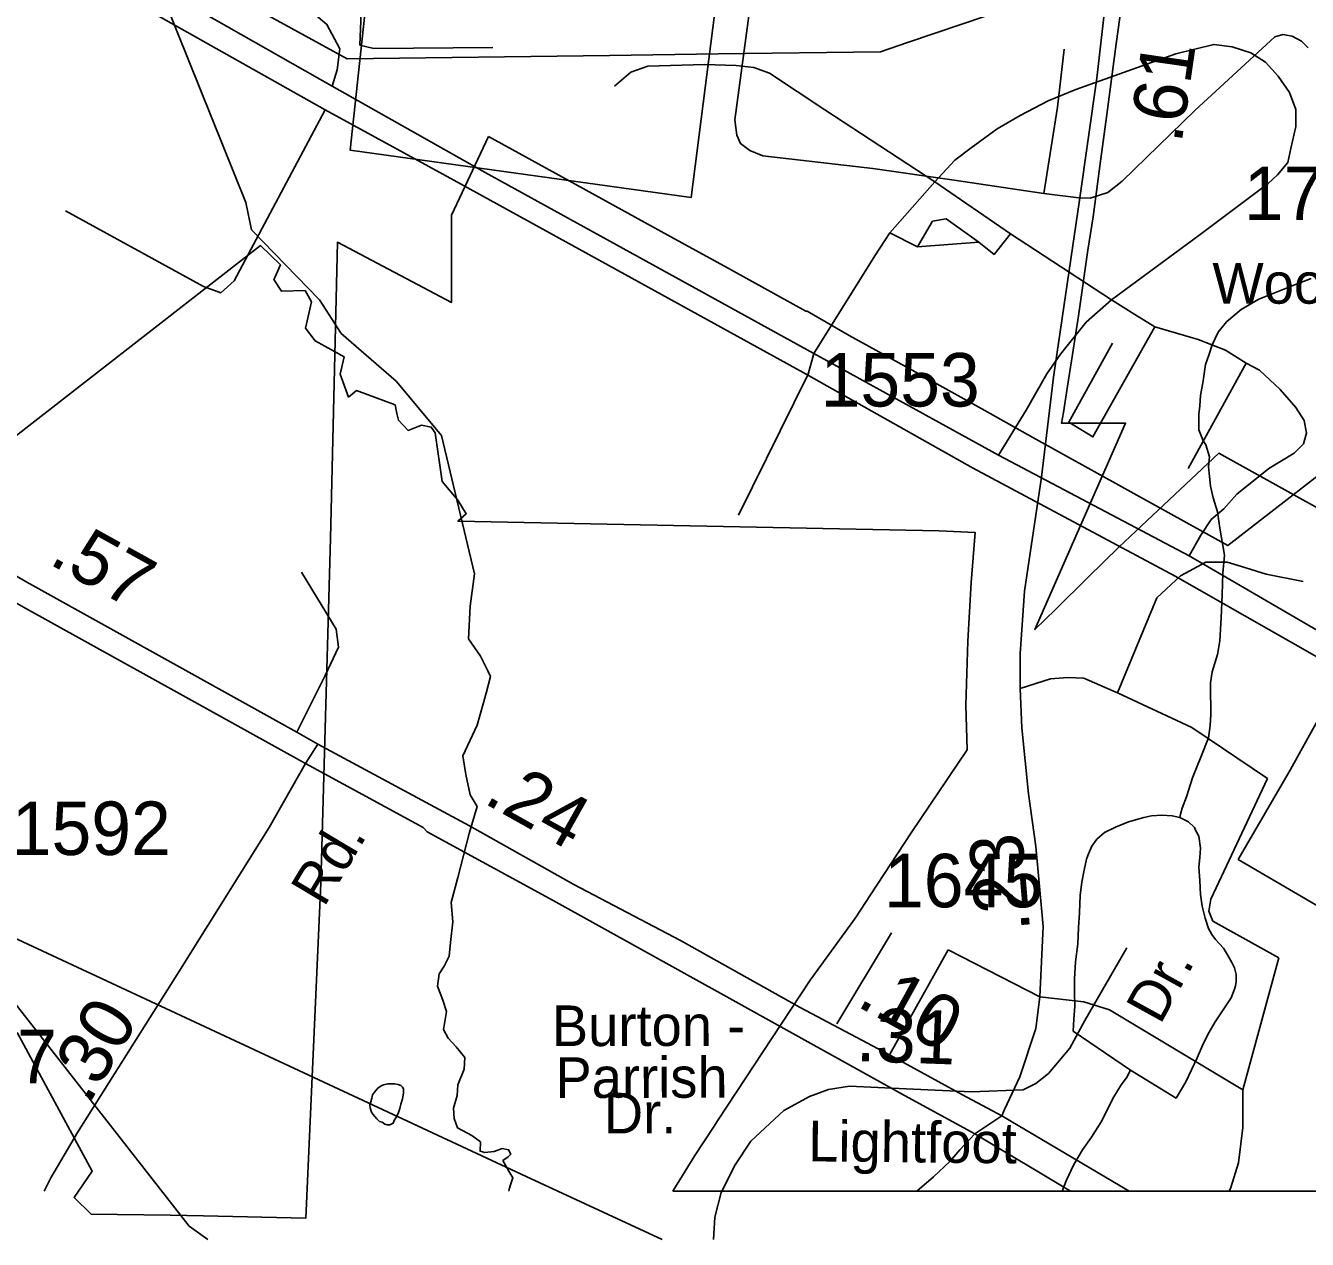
# Model space of a CAD drawing. Extents: x 2169602 to 2449496, y 721995 to 810662.
# Drawn here: x 2392905 to 2395899, y 758895 to 761731 of the extents above; entities that cross this region are included whole.
import ezdxf

# ---------------------------------------------------------------- set-up
doc = ezdxf.new("R2010")
doc.units = 0
doc.layers.add('Default', color=7, linetype='Continuous')

msp = doc.modelspace()

# ---------------------------------------------------------------- linework, layer by layer
at = {"layer": 'Default'}
for p, q in [((2393694.4, 761900.1), (2393685.4, 761684.9)), ((2394923.5, 761246.5), (2395028.4, 761365.8)), ((2395205.6, 761244.7), (2395028.4, 761365.8)), ((2394988.6, 761213.9), (2395022.9, 761273.6)), ((2395022.9, 761273.6), (2395055.5, 761279)), ((2395055.5, 761279), (2395131.5, 761224.8)), ((2394923.5, 761246.5), (2394988.6, 761213.9)), ((2395167.6, 761195.9), (2395205.6, 761244.7)), ((2395205.6, 761244.7), (2395441.6, 761090.1)), ((2394988.6, 761213.9), (2395131.5, 761224.8)), ((2395131.5, 761224.8), (2395167.6, 761195.9)), ((2395756.3, 760941.8), (2395620.6, 760695.8)), ((2394799.7, 759398.8), (2394927.2, 759611.2)), ((2395060.1, 759571.5), (2394923.1, 759326.2)), ((2395274.4, 759461.5), (2395060.1, 759571.5)), ((2395748.1, 759244.5), (2395832.6, 759552.6)), ((2394416.8, 759007.9), (2405610.9, 759007.9)), ((2394416.8, 759007.9), (2405610.9, 759007.9))]:
    msp.add_line(p, q, dxfattribs=at)
for points in [[(2393587.2, 760051.8), (2393538.6, 760080.4), (2392907.2, 760430.4), (2392607.1, 760604.7), (2392161.9, 760840.1), (2391730.4, 761078), (2390962.6, 761500.1), (2390605.2, 761701.9), (2389990.5, 762051.8), (2389856.7, 762127.7), (2389737.8, 762198.8), (2389440.2, 762351.9), (2389076.5, 762551.2), (2388547.4, 762852.9), (2388224.1, 763014.5), (2387185.5, 763596), (2386852.4, 763781.6), (2386637.1, 763912.4), (2386426.2, 764027.4), (2386153.7, 764163.9)], [(2386150.4, 764102.4), (2386756.5, 763764.2), (2388207.3, 762942.2), (2388747.6, 762648.7), (2389706.7, 762136.5), (2390036.6, 761958.6), (2390589, 761647.1), (2390889.1, 761482.7), (2391705.4, 761033.1), (2392100.8, 760810.2), (2392574.7, 760557.4), (2392899.7, 760371.9), (2393558.4, 760007.1)], [(2396603, 759939), (2396554.4, 759967.6), (2395923, 760317.6), (2395622.9, 760491.9), (2395177.7, 760727.3), (2394746.2, 760965.1), (2393978.4, 761387.3), (2393621, 761589.1), (2393006.3, 761938.9), (2392872.5, 762014.9), (2392753.6, 762085.9), (2392456, 762239.1), (2392092.4, 762438.4), (2391563.2, 762740), (2391239.9, 762901.6), (2390201.3, 763483.2), (2389868.2, 763668.8), (2389653, 763799.6), (2389442, 763914.6), (2389169.5, 764051.1)], [(2389166.2, 763989.6), (2389772.3, 763651.3), (2391223.1, 762829.4), (2391763.5, 762535.9), (2392722.5, 762023.7), (2393052.4, 761845.8), (2393604.8, 761534.3), (2393905, 761369.9), (2394721.3, 760920.3), (2395116.7, 760697.4), (2395590.5, 760444.6), (2395915.6, 760259), (2396574.3, 759894.3)], [(2395185.2, 759183.4), (2395191.7, 759198.2), (2395227.3, 759274.7), (2395264.6, 759388), (2395274.4, 759461.5), (2395282.1, 759625.9), (2395264.6, 759812.7), (2395247.5, 759935.8), (2395231.7, 760090.3), (2395228, 760182.1), (2395228, 760263.3), (2395237.9, 760409.1), (2395277.7, 760675.8), (2395305.8, 760909.3), (2395366.7, 761322.6), (2395407, 761608.2), (2395431.6, 761819.5), (2395459.4, 762022.6), (2395487.1, 762218), (2395516.8, 762436.2), (2395579.2, 762896), (2395622.1, 763235.2), (2395654.9, 763535.4)], [(2395928.5, 762403.9), (2395891.5, 762227.2), (2395845.2, 762019.2), (2395840.7, 761986.6), (2395737, 761951.6), (2395433.7, 761849.2), (2395211.5, 761774.3), (2394965.2, 761691.2), (2394902, 761669.9), (2394522.2, 761664.7), (2394268.7, 761661.2), (2393656, 761652.8), (2393320.5, 761837.6), (2393242.7, 761881.4), (2393240.7, 761882.4), (2393165.7, 761922.9), (2392899.5, 762066.6)], [(2395928.5, 762403.9), (2395891.5, 762227.2), (2395845.2, 762019.2), (2395840.7, 761986.6), (2395737, 761951.6), (2395433.7, 761849.2), (2395211.5, 761774.3), (2394965.2, 761691.2), (2394902, 761669.9), (2394522.2, 761664.7), (2394268.7, 761661.2), (2393656, 761652.8), (2393320.5, 761837.6), (2393242.7, 761881.4), (2393240.7, 761882.4), (2393165.7, 761922.9), (2392899.5, 762066.6)], [(2393424.1, 761949.8), (2393444.9, 761900.1), (2393470.2, 761858.5), (2393506.4, 761820.5), (2393608.6, 761733.5), (2393626, 761699.9), (2393638.4, 761676.2), (2393632.2, 761627.7), (2393621, 761589.1)], [(2395283.6, 761338.5), (2395073.9, 761369.6), (2394883.9, 761396.9), (2394627.3, 761426.9), (2394596.7, 761438.9), (2394574.9, 761455.3), (2394566.1, 761475), (2394561.8, 761511), (2394608.7, 761864.3)], [(2396107.2, 760501.1), (2395692.4, 760731.8), (2395511.4, 760562.1), (2395458.4, 760512.6), (2395387.2, 760442.5), (2395310.4, 760366.8), (2395262.7, 760319.8), (2395474.2, 760801.9), (2395324.9, 760801.9), (2395329.2, 760827.1), (2395338.4, 760888.4), (2395350.2, 760962.5), (2395364.7, 761053.1), (2395386.4, 761206.4), (2395398.4, 761283.7), (2395408.7, 761361.5), (2395413.9, 761402.2), (2395430.2, 761523.5), (2395452.4, 761688.3), (2395472.7, 761834.5)], [(2396107.2, 760501.1), (2395692.4, 760731.8), (2395511.4, 760562.1), (2395458.4, 760512.6), (2395387.2, 760442.5), (2395310.4, 760366.8), (2395262.7, 760319.8), (2395474.2, 760801.9), (2395324.9, 760801.9), (2395329.2, 760827.1), (2395338.4, 760888.4), (2395350.2, 760962.5), (2395364.7, 761053.1), (2395386.4, 761206.4), (2395398.4, 761283.7), (2395408.7, 761361.5), (2395413.9, 761402.2), (2395430.2, 761523.5), (2395452.4, 761688.3), (2395472.7, 761834.5)], [(2394034.4, 759007.9), (2394033.7, 759009), (2394036.8, 759020), (2394042.9, 759038.8), (2394033.7, 759054), (2394019.7, 759079), (2394031.9, 759087.5), (2394038.6, 759094.2), (2394033.1, 759104.6), (2394017.9, 759107), (2393999.1, 759100.3), (2393977.1, 759097.9), (2393966.2, 759100.9), (2393967.4, 759122.8), (2393947.3, 759137.4), (2393913.8, 759155.7), (2393905.9, 759177.6), (2393904.1, 759201.9), (2393912.6, 759231.1), (2393914.5, 759256.1), (2393929.1, 759292.6), (2393930.9, 759320), (2393910.2, 759344.9), (2393891.9, 759365), (2393881, 759385.1), (2393887.7, 759427.1), (2393879.2, 759453.9), (2393867, 759486.8), (2393870.6, 759515.4), (2393882.8, 759533.6), (2393894.4, 759556.7), (2393897.4, 759589), (2393902.9, 759637.1), (2393899.2, 759682.1), (2393914.7, 759740.5), (2393940.5, 759843.5), (2393959.5, 759906.1), (2393943.3, 759933.5), (2393933.4, 759980.8), (2393925.9, 760024.4), (2393959.5, 760096.6), (2393980.7, 760171.4), (2393990.6, 760210), (2393984.4, 760223.7), (2393967, 760257.3), (2393939.6, 760298.4), (2393943.3, 760374.3), (2393953.5, 760449.9), (2393876.6, 760772.8), (2393770.6, 760900.1), (2393642.2, 761011.5), (2393591.6, 761090.3), (2393432.4, 761253.3), (2393419.5, 761317.5), (2393231.2, 761784.2)], [(2393685.4, 761684.9), (2393717.9, 761677.6), (2393996.4, 761679.4)], [(2395441.6, 761090.1), (2395648.7, 761242.9), (2395807.8, 761362.2), (2395829.5, 761382.1), (2395853, 761411.1), (2395860.2, 761443.6), (2395872, 761495.1), (2395872, 761534.9), (2395857.5, 761574.7), (2395830.4, 761612.7), (2395801.5, 761645.2), (2395767.1, 761666.9), (2395723.7, 761681.4), (2395680.3, 761686.8), (2395591.7, 761665.1), (2395358.4, 761581.9), (2395293.3, 761554.8), (2395228.2, 761520.5), (2395174, 761489.7), (2395113.4, 761445.4), (2395075.4, 761416.5), (2395028.4, 761365.8)], [(2395391.7, 761327.5), (2395433.2, 761341.2), (2395466, 761367.4), (2395636.3, 761532.3), (2395823.1, 761704.3), (2395841.6, 761709.8), (2395863.5, 761706.5), (2395885.3, 761694.5), (2395900.6, 761679.2)], [(2395283.6, 761338.5), (2395315.3, 761540.5), (2395330.6, 761675.4)], [(2395028.4, 761365.8), (2394771.6, 761534), (2394642.3, 761619.9), (2394606.1, 761632.6), (2394564.5, 761638), (2394490.4, 761639.8), (2394358.4, 761636.2), (2394318.6, 761621.7), (2394280.6, 761589.2)], [(2393604.8, 761534.3), (2393391.9, 761134.5), (2393360.4, 761106.3), (2393320.6, 761121.2), (2392997.6, 761298.4)], [(2392884.7, 759378.6), (2393060.5, 759054.6), (2393018, 758993.1), (2393058, 758954.1), (2393242.7, 758951.2), (2393320.5, 758950), (2393559.2, 758944.4), (2393594, 759727.2), (2393616.7, 760532.9), (2393633, 761224.7), (2393899.7, 761084.1), (2393899.5, 761288.2), (2393985.7, 761471.5)], [(2392884.7, 759378.6), (2393060.5, 759054.6), (2393018, 758993.1), (2393058, 758954.1), (2393242.7, 758951.2), (2393320.5, 758950), (2393559.2, 758944.4), (2393594, 759727.2), (2393616.7, 760532.9), (2393633, 761224.7), (2393899.7, 761084.1), (2393899.5, 761288.2), (2393985.7, 761471.5)], [(2393985.7, 761471.5), (2394174.2, 761368.2), (2394366.7, 761262.6), (2394405.2, 761241.4), (2394544.7, 761164.9)], [(2393985.7, 761471.5), (2394174.2, 761368.2), (2394366.7, 761262.6), (2394405.2, 761241.4), (2394544.7, 761164.9)], [(2395391.7, 761327.5), (2395365.5, 761328.6), (2395283.6, 761338.5)], [(2394746.2, 760965.1), (2394888.2, 761193.1), (2394923.5, 761246.5)], [(2392697.2, 760628.6), (2392912.2, 760795.9), (2393453.4, 761217), (2393500.2, 761171.6), (2393487.9, 761144.1), (2393484.9, 761137.3), (2393502.4, 761110.6), (2393557.4, 761111.9), (2393572.9, 761085.7), (2393558.2, 761024.1), (2393580.9, 760994.2), (2393648.9, 760956.9), (2393639.2, 760916.5), (2393659.2, 760862.9), (2393677.9, 760878.1), (2393767.7, 760844.5), (2393772.2, 760824.3), (2393775.4, 760808.8), (2393798.7, 760785), (2393829.7, 760797.3), (2393852.4, 760792.9), (2393861.7, 760779.6), (2393877.9, 760666), (2393914.4, 760621.9), (2393934.2, 760590.4), (2393914.4, 760572.8), (2395038.7, 760550.1), (2395123.2, 760546.5), (2395113.4, 760429.4), (2395105.9, 760292.8), (2395101.2, 760142.8), (2395103.9, 760038.8), (2394973.7, 759845), (2394878.7, 759699.7), (2394843.4, 759646), (2394737.2, 759500.7), (2394627.7, 759334), (2394522.4, 759174.1), (2394511.4, 759157.3), (2394467.7, 759090.9), (2394416.8, 759007.9)], [(2392697.2, 760628.6), (2392912.2, 760795.9), (2393453.4, 761217), (2393500.2, 761171.6), (2393487.9, 761144.1), (2393484.9, 761137.3), (2393502.4, 761110.6), (2393557.4, 761111.9), (2393572.9, 761085.7), (2393558.2, 761024.1), (2393580.9, 760994.2), (2393648.9, 760956.9), (2393639.2, 760916.5), (2393659.2, 760862.9), (2393677.9, 760878.1), (2393767.7, 760844.5), (2393772.2, 760824.3), (2393775.4, 760808.8), (2393798.7, 760785), (2393829.7, 760797.3), (2393852.4, 760792.9), (2393861.7, 760779.6), (2393877.9, 760666), (2393914.4, 760621.9), (2393934.2, 760590.4), (2393914.4, 760572.8), (2395038.7, 760550.1), (2395123.2, 760546.5), (2395113.4, 760429.4), (2395105.9, 760292.8), (2395101.2, 760142.8), (2395103.9, 760038.8), (2394973.7, 759845), (2394878.7, 759699.7), (2394843.4, 759646), (2394737.2, 759500.7), (2394627.7, 759334), (2394522.4, 759174.1), (2394511.4, 759157.3), (2394467.7, 759090.9), (2394416.8, 759007.9)], [(2394544.7, 761164.9), (2394558.7, 761157.1), (2394727, 761063.7), (2394730.5, 761063.4), (2394828.7, 761007.1), (2394991, 760916.9), (2395145.5, 760831.2), (2395257.7, 760768.7), (2395544.5, 760609.4), (2395713, 760515.8), (2395928, 760683.1)], [(2394544.7, 761164.9), (2394558.7, 761157.1), (2394727, 761063.7), (2394730.5, 761063.4), (2394828.7, 761007.1), (2394991, 760916.9), (2395145.5, 760831.2), (2395257.7, 760768.7), (2395544.5, 760609.4), (2395713, 760515.8), (2395928, 760683.1)], [(2395907.7, 761140.1), (2395871.4, 761126.2), (2395835.9, 761111.7), (2395785.7, 761091.7), (2395744.3, 761067.5), (2395710.2, 761039), (2395690.5, 761014.8), (2395676.6, 760984.8), (2395668.8, 760960.9), (2395660.8, 760939), (2395655.5, 760900.9), (2395649.3, 760866.9), (2395647.5, 760842.8), (2395645.4, 760822.9), (2395645.6, 760808.6), (2395645.8, 760786.7), (2395652, 760770.8), (2395655.9, 760760.9), (2395661.8, 760751), (2395670.4, 760723), (2395668, 760701), (2395670.4, 760677.2), (2395672.7, 760654.9), (2395678.6, 760627.2), (2395689.1, 760595.2), (2395694.6, 760557), (2395705.7, 760493.3), (2395701.6, 760451.3), (2395700.2, 760401.3), (2395697.9, 760347.3), (2395694.4, 760293.4), (2395688.7, 760261.5), (2395676.8, 760221.1), (2395673.1, 760195.3), (2395673.1, 760167.3), (2395673.3, 760141.3), (2395673.5, 760121.4), (2395671.7, 760095.3), (2395667.8, 760067.1), (2395652, 760025.3), (2395640.1, 759997), (2395630.5, 759973), (2395616.7, 759928.8), (2395606.5, 759902.8), (2395602.8, 759888.7), (2395601.1, 759880.8)], [(2395441.6, 761090.1), (2395381.9, 761037.6), (2395322.2, 760963.5), (2395290.6, 760917.4), (2395241.8, 760832.4), (2395177.7, 760727.3)], [(2395441.6, 761090.1), (2395495.8, 761055.7), (2395542.9, 761026.8)], [(2395542.9, 761026.8), (2395398.2, 760770), (2395342.1, 760804.3), (2395443.4, 760988.8)], [(2395542.9, 761026.8), (2395644.1, 760997.8), (2395707.4, 760972.5), (2395756.3, 760941.8)], [(2394746.2, 760965.1), (2394732.5, 760916.6), (2394569.9, 760587.3)], [(2395756.3, 760941.8), (2395787, 760925.5), (2395835.8, 760880.3), (2395872, 760838.7), (2395891.9, 760808), (2395897.3, 760779), (2395890.1, 760753.7), (2395868.4, 760732), (2395808.7, 760695.8), (2395734.6, 760636.2), (2395703.8, 760601.5), (2395674, 760576.6), (2395650.3, 760540.5), (2395622.9, 760491.9)], [(2393330.7, 758895), (2393286.4, 758926), (2392606.4, 759796), (2392447.3, 759969.9), (2392255.4, 760059.1), (2392045.4, 760316), (2391847.4, 760509.1)], [(2395455.3, 760171.8), (2395547.7, 760394.1), (2395602.3, 760445.5), (2395662, 760477), (2395711.7, 760477), (2395744.8, 760467), (2395802.8, 760448.8), (2395888.9, 760432.2)], [(2393538.6, 760080.4), (2393604.6, 760212.5), (2393635.7, 760278.5), (2393630.1, 760320.8), (2393549.2, 760454.1)], [(2395228, 760182.1), (2395298.6, 760204.6), (2395339.7, 760207.4), (2395376.7, 760206), (2395426.5, 760184.1), (2395455.3, 760171.8)], [(2395455.3, 760171.8), (2395628.9, 760090.9), (2395806.1, 759971.7)], [(2396056.2, 759596.7), (2395737.7, 759782.8), (2395859.9, 759993.1), (2395939.7, 760137.5)], [(2396056.2, 759596.7), (2395737.7, 759782.8), (2395859.9, 759993.1), (2395939.7, 760137.5)], [(2394391.7, 758895), (2394074.2, 759042.1), (2392504.6, 759773.1), (2391847, 760099.2)], [(2393587.2, 760051.8), (2393558.4, 760007.1)], [(2395185.2, 759183.4), (2395093.2, 759232.4), (2394923.1, 759326.2), (2394714.2, 759436.6), (2394434.6, 759593.5), (2394185.5, 759724.3), (2393941.5, 759861.3), (2393587.2, 760051.8)], [(2393558.4, 760007.1), (2393473.8, 759857.5), (2393258.4, 759514.1), (2393025.9, 759144.7), (2392963.8, 759038.8), (2392947.8, 759007.9)], [(2393558.4, 760007.1), (2393833.1, 759857.5), (2393842.6, 759847), (2394137, 759686.9), (2394549.8, 759457.8), (2394957.6, 759231.1), (2395122, 759141.5)], [(2395832.6, 759552.6), (2395678.5, 759638.8), (2395668.6, 759662), (2395673.6, 759690.1), (2395691.8, 759729.9), (2395806.1, 759971.7)], [(2395601.1, 759880.8), (2395583.1, 759884.8), (2395558.7, 759886.5), (2395534.9, 759884.4), (2395516.9, 759880.6), (2395481.2, 759870.2), (2395451, 759858.1), (2395425.2, 759845.8), (2395407.4, 759829.9), (2395395.3, 759813.8), (2395387.5, 759795.5), (2395383.4, 759783.6), (2395377.4, 759757.7), (2395371.9, 759729.8), (2395368.2, 759699.5), (2395366.3, 759657.6), (2395364.5, 759623.8), (2395362.9, 759585.5), (2395357.1, 759543.8), (2395355.1, 759503.5), (2395355.3, 759471.4), (2395355.5, 759439.8), (2395353.4, 759409.7), (2395351.8, 759381.5), (2395486.1, 759290.2)], [(2395486.1, 759290.2), (2395592.5, 759225.1), (2395614.7, 759263.1), (2395641.9, 759319.4), (2395656.1, 759353.4), (2395669.6, 759379.3), (2395683.6, 759403.6), (2395720.9, 759459.6), (2395728.9, 759479.9), (2395731.1, 759487.6), (2395732.8, 759497.9), (2395733, 759513.7), (2395728.7, 759529.8), (2395722.7, 759541.6), (2395712.5, 759559.8), (2395702.8, 759575.5), (2395684.4, 759595.3), (2395676.2, 759607.4), (2395668.4, 759621.2), (2395660, 759645.2), (2395653.6, 759673.4), (2395649.7, 759701.1), (2395647.5, 759733.1), (2395645.6, 759765), (2395647.5, 759787), (2395649.1, 759809.1), (2395645.2, 759837.3), (2395638.7, 759849.2), (2395635, 759857.1), (2395621, 759870.9), (2395601.1, 759880.8)], [(2394511.8, 758895), (2394514.5, 758946.6), (2394529.8, 759004.5), (2394562.5, 759068.9), (2394598.6, 759124.6), (2394675.6, 759196.1), (2394735.6, 759228.9), (2394780.4, 759245.3), (2394829.5, 759252.9), (2394961.7, 759246.6), (2395114.1, 759240.1), (2395235.1, 759244.1), (2395264.7, 759258.9), (2395294.2, 759282.9), (2395343.9, 759341.4), (2395379.4, 759406.3), (2395477.1, 759576.1)], [(2395274.4, 759461.5), (2395377.1, 759449.9), (2395436.7, 759431.7), (2395748.1, 759244.5)], [(2395486.1, 759290.2), (2395476.3, 759272.2), (2395464.4, 759256.2), (2395446.9, 759228.1), (2395426.6, 759188.1), (2395418.8, 759172.2), (2395395.1, 759134), (2395373.5, 759104), (2395353.4, 759069.8), (2395335.6, 759031.5), (2395325.8, 759007.9)], [(2393780.9, 759210.6), (2393785.2, 759223), (2393787.4, 759236.8), (2393787.2, 759243), (2393787.4, 759247), (2393785, 759250.6), (2393781.1, 759254.9), (2393774.9, 759256.6), (2393766.7, 759258.6), (2393760.8, 759258.7), (2393751.2, 759258.6), (2393740.9, 759256.4), (2393736.8, 759254.6), (2393733.1, 759252.3), (2393727.4, 759248.4), (2393719.4, 759238.6), (2393715.3, 759232.4), (2393713.2, 759224.6), (2393711.4, 759216.3), (2393709.1, 759208.5), (2393709.5, 759202.4), (2393711.6, 759194.4), (2393713.4, 759190.4), (2393719.4, 759182.6), (2393725.5, 759176.4), (2393731.3, 759170.7), (2393737.4, 759168.6), (2393743.6, 759164.4), (2393749.5, 759162.6), (2393755.5, 759162.6), (2393763.5, 759166.6), (2393765.7, 759172.8), (2393769.2, 759178.7), (2393775.1, 759188.8), (2393779.2, 759200.8), (2393780.9, 759210.6)], [(2395748.1, 759244.5), (2395748.1, 759156.7), (2395738.2, 759073.9), (2395720, 759015.9), (2395716.2, 759007.9)], [(2395122, 759141.5), (2395185.2, 759183.4)], [(2395482.8, 759007.9), (2395185.2, 759183.4)], [(2394986.7, 759007.9), (2395025.4, 759041.4), (2395064, 759076.7), (2395087.3, 759104.2), (2395122, 759141.5)], [(2395122, 759141.5), (2395345.6, 759007.9)]]:
    msp.add_lwpolyline(points, dxfattribs=at)
msp.add_lwpolyline([(2393506, 763296.5), (2393395.5, 762315.2), (2393754.8, 762269.1), (2393750.2, 762227.7), (2394086.5, 762181.6), (2394068.1, 762089.5), (2393648.9, 762154), (2393625.8, 761942), (2393870, 761914.4), (2393865.4, 761891.4), (2393713.4, 761909.8), (2393662.7, 761439.9), (2394459.7, 761329.3), (2394528.8, 761872.9), (2394630.1, 761859.1), (2394653.2, 761992.7), (2394561, 762006.5), (2394579.5, 762112.5), (2394998.7, 762057.2), (2395104.7, 762863.4), (2394620.9, 762932.5), (2394639.4, 763121.4)], close=True, dxfattribs=at)

# ---------------------------------------------------------------- texts
for s, height, rotation, p in [('.61', 125, 81.775, (2395604.9, 761453.4)), ('.57', 125, 331.003, (2392955.8, 760474.9)), ('.24', 125, 330.6978, (2393971.4, 759916.2)), ('Rd.', 95, 59.0652, (2393601.6, 759668.9)), ('.23', 125, 94.7357, (2395251.4, 759615.8)), ('Dr.', 95, 61.1526, (2395555.1, 759394.6)), ('.10', 125, 331.138, (2394842.8, 759441.8)), ('.30', 125, 59.5295, (2393052.2, 759208.1)), ('Burton -', 95, 0.1025, (2394134, 759346.5)), ('.31', 125, 357.989, (2394843.3, 759311.7)), ('Parrish', 95, 0.1025, (2394142.5, 759225.3)), ('Dr.', 95, 0.1025, (2394255.6, 759142.4)), ('Lightfoot', 95, 359.4204, (2394732.5, 759077.4))]:
    msp.add_text(s, height=height, rotation=rotation, dxfattribs=at).set_placement(p)
for s, height, p in [('1765', 125, (2395750.4, 761276.3)), ('Woodcrest', 95, (2395677.2, 761081.1)), ('1553', 125, (2394761.8, 760840.9)), ('1592', 125, (2392872.1, 759793)), ('1645', 125, (2394909.9, 759670.8)), ('1807', 125, (2392606, 759259.7))]:
    msp.add_text(s, height=height, dxfattribs=at).set_placement(p)

doc.saveas('drawing.dxf')
